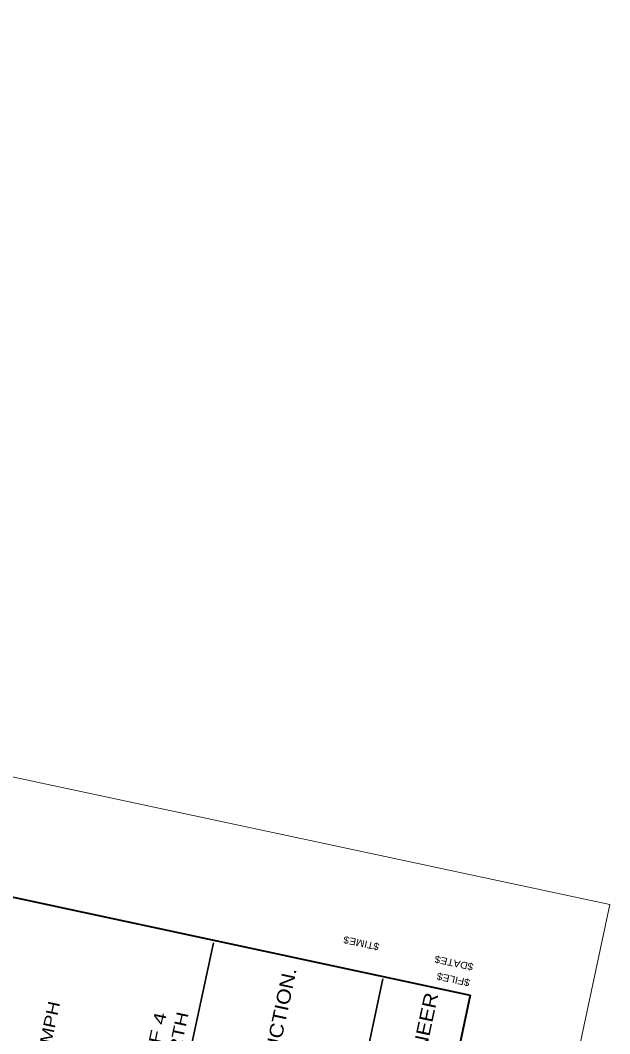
# Model space of a CAD drawing. Extents: x 2363411 to 2369126, y 6976878 to 6988319.
# Drawn here: x 2368624 to 2369126, y 6987356 to 6988218 of the extents above; entities that cross this region are included whole.
import ezdxf
from ezdxf.enums import TextEntityAlignment as Align

# ---------------------------------------------------------------- set-up
doc = ezdxf.new("R2010")
doc.units = 0
doc.header["$LTSCALE"] = 2
for name, color, linetype, lineweight in [('44', 7, 'Continuous', 40), ('62', 7, 'Continuous', 13), ('63', 7, 'Continuous', 13)]:
    doc.layers.add(name, color=color, linetype=linetype, lineweight=lineweight)
doc.layers.add('60', color=7, linetype='Continuous')

msp = doc.modelspace()

# ---------------------------------------------------------------- linework, layer by layer
at = {"layer": '44', "lineweight": 13}
msp.add_line((2365605.51, 6988218.434), (2369126.202, 6987466.173), dxfattribs=at)
at = {"layer": '44'}
msp.add_line((2365682.411, 6988099.741), (2369007.509, 6987389.272), dxfattribs=at)
at = {"layer": '62'}
msp.add_line((2369126.202, 6987466.173), (2366932.108, 6977197.487), dxfattribs=at)
at = {"layer": '62', "lineweight": 35}
for p, q in [((2368788.776, 6987433.781), (2368652.739, 6986797.1)), ((2368933.065, 6987402.951), (2368879.741, 6987153.387))]:
    msp.add_line(p, q, dxfattribs=at)
at = {"layer": '62', "lineweight": 40}
msp.add_line((2369007.509, 6987389.272), (2366855.207, 6977316.18), dxfattribs=at)
at = {"layer": '63'}
msp.add_line((2369126.202, 6987466.173), (2366932.108, 6977197.487), dxfattribs=at)
at = {"layer": '63', "lineweight": 40}
msp.add_line((2369007.509, 6987389.272), (2366855.207, 6977316.18), dxfattribs=at)

# ---------------------------------------------------------------- texts
at = {"layer": '60', "width": 1.1}
for s, p in [('$TIME$', (2368930.476, 6987432.967)), ('$DATE$', (2369010.632, 6987415.84)), ('$FILE$', (2369007.619, 6987402.382))]:
    msp.add_text(s, height=6, rotation=167.939, dxfattribs=at).set_placement(p)
at = {"layer": '62', "width": 1.15}
for s, p in [('NOT FOR CONSTRUCTION.', (2368810.32, 6987179.743)), ('TxDOT DISTRICT ENGINEER', (2368928.993, 6987149.515))]:
    msp.add_text(s, height=11.74, rotation=77.939, dxfattribs=at).set_placement(p)
at = {"layer": '62'}
for s, width, p in [('FRONTAGE ROAD DESIGN SPEED VARIABLE 35 TO 40 MPH', 1.2, (2368609.509, 6987153.607)), ('ROLL 2 OF 4', 1.35, (2368737.618, 6987319.718)), ('IH 820 NORTH', 1.25, (2368755.732, 6987317.124))]:
    msp.add_text(s, height=10.2, rotation=77.939, dxfattribs=dict(at, width=width)).set_placement(p, align=Align.CENTER)

doc.saveas('drawing.dxf')
